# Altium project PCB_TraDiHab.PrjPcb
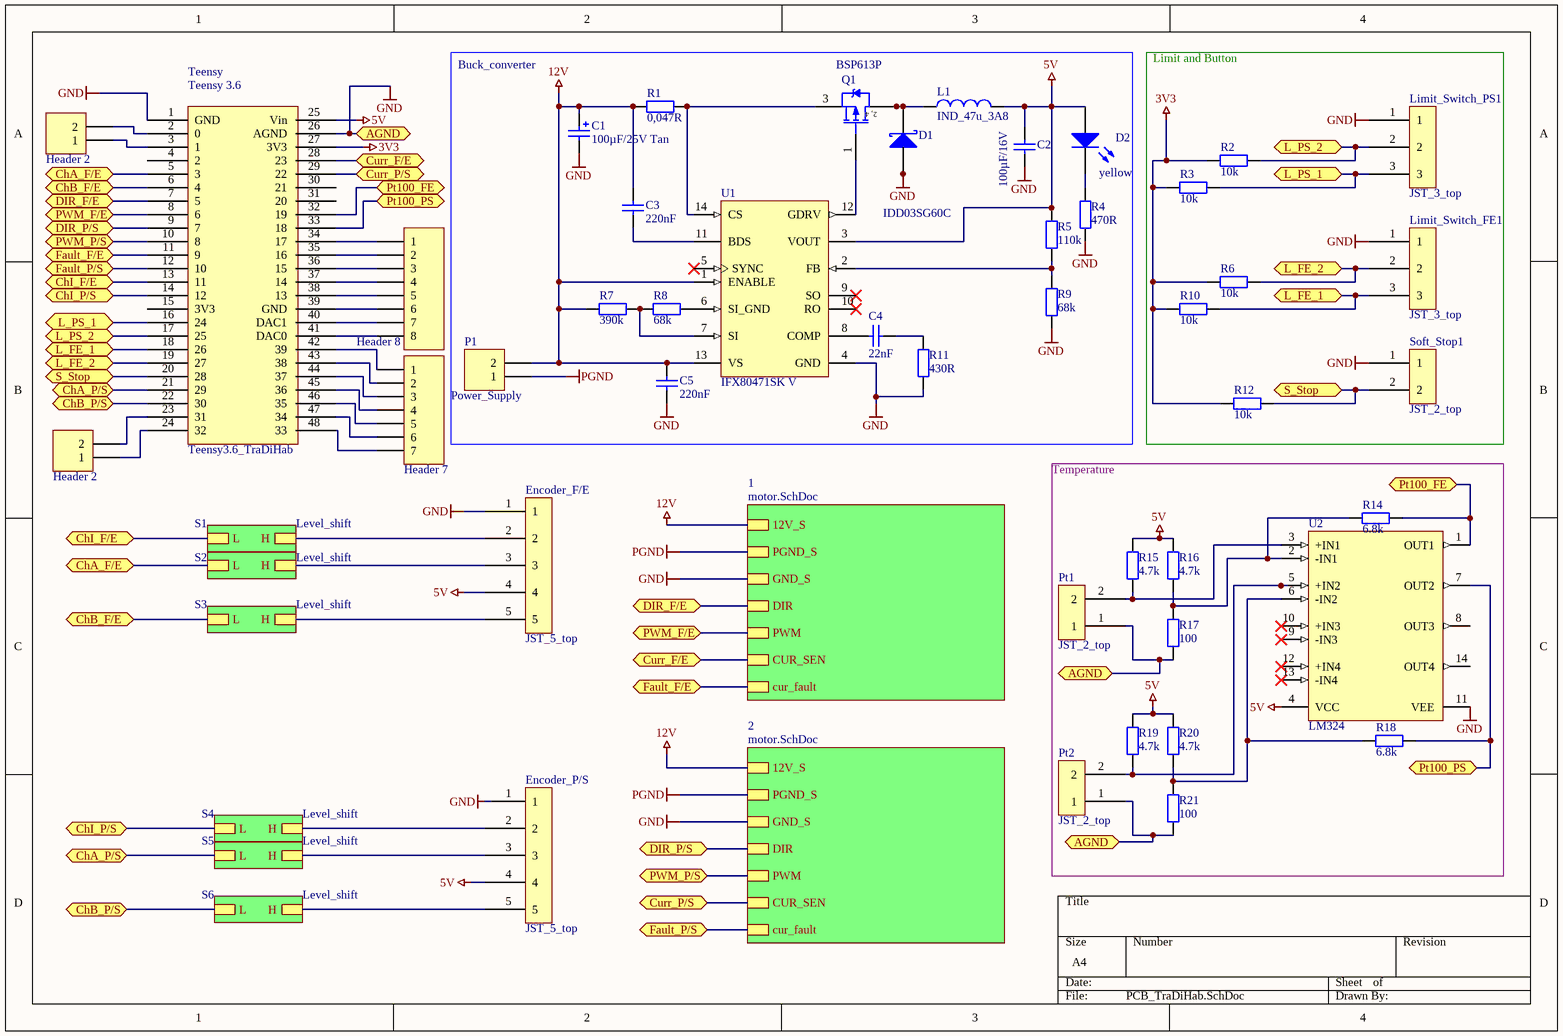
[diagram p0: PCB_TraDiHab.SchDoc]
3 sheets, 122 parts. Net scope: hierarchical (ports join the sheet entries above them; power ports are global).
Board file: 6C-2L-1550um.PcbDoc
Sheets:
  PCB_TraDiHab.SchDoc
    1 = motor.SchDoc
    2 = motor.SchDoc
    S1 = Level_shift.SchDoc
    S2 = Level_shift.SchDoc
    S3 = Level_shift.SchDoc
    S5 = Level_shift.SchDoc
    S6 = Level_shift.SchDoc
    S4 = Level_shift.SchDoc

## Sheet PCB_TraDiHab.SchDoc
size A4

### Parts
C1  100µF/25V Tan  [C]
C2  100µF/16V  [_1210]
C3  220nF  [_0805]
C4  22nF  [_0805]
C5  220nF  [_0805]
D1  IDD03SG60C  [TO_252]
D2  yellow  [LED_SMD]
Encoder_F/E  JST_5_top  [JST_5_top]
Encoder_P/S  JST_5_top  [JST_5_top]
L1  IND_47u_3A8  [WE_PD_XXL]
Limit_Switch_FE1  JST_3_top  [JST_3_top]
Limit_Switch_PS1  JST_3_top  [JST_3_top]
P1  Power_Supply  [WRTBL_2P_508]
P3  Header 8  [HDR1X8]
P4  Header 7  [HDR1X7]
P5  Header 2  [HDR1X2]
P6  Header 2  [HDR1X2]
Pt1  JST_2_top  [JST_2_top]
Pt2  JST_2_top  [JST_2_top]
Q1  BSP613P  [INF-PG-SOT223_SC-73_N]
R1  0,047R  [_1206]
R2  10k  [_0805]
R3  10k  [_0805]
R4  470R  [_0805]
R5  110k  [_0805]
R6  10k  [_0805]
R7  390k  [_0805]
R8  68k  [_0805]
R9  68k  [_0805]
R10  10k  [_0805]
R11  430R  [_0805]
R12  10k  [_0805]
R14  6.8k  [_0805]
R15  4.7k  [_0805]
R16  4.7k  [_0805]
R17  100  [_0805]
R18  6.8k  [_0805]
R19  4.7k  [_0805]
R20  4.7k  [_0805]
R21  100  [_0805]
Soft_Stop1  JST_2_top  [JST_2_top]
Teensy  Teensy3.6_TraDiHab  [teensy3_6footprint]
U1  IFX80471SK V  [INF-PG-DSO-14-1_N]
U2  LM324  [SO_14]

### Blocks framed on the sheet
Buck_converter: C1-C5 D1 D2 L1 P1 Q1 R1 R4 R5 R7-R9 R11 U1
Limit and Button: Limit_Switch_FE1 Limit_Switch_PS1 R2 R3 R6 R10 R12 Soft_Stop1
Temperature: Pt1 Pt2 R14-R21 U2

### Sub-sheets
1 = motor.SchDoc: PGND_S, GND_S, PWM, CUR_SEN, DIR, 12V_S, cur_fault
2 = motor.SchDoc: PGND_S, GND_S, PWM, CUR_SEN, DIR, 12V_S, cur_fault
S1 = Level_shift: L, H
S2 = Level_shift: L, H
S3 = Level_shift: L, H
S4 = Level_shift: L, H
S5 = Level_shift: L, H
S6 = Level_shift: L, H

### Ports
AGND, ChA_F/E, ChA_P/S, ChB_F/E, ChB_P/S, ChI_F/E, ChI_P/S, Curr_F/E, Curr_P/S, DIR_F/E, DIR_P/S, Fault_F/E, Fault_P/S, L_FE_1, L_FE_2, L_PS_1, L_PS_2, Pt100_FE, Pt100_PS, PWM_F/E, PWM_P/S, S_Stop

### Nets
3V3: R2.1 R3.1 R6.1 R10.1 R12.1 Teensy.27(3V3)
5V: C2.2 D2.1 Encoder_F/E.4 Encoder_P/S.4 L1.2 R5.2 R15.2 R16.2 R19.2 R20.2 Teensy.25(Vin) U1.3(VOUT) U2.4(VCC)
12V: C1.1 C3.2 C5.2 P1.2 R1.1 R7.1 U1.1(ENABLE) U1.13(VS) ; sheet 1/12V_S, sheet 2/12V_S  [project net V+]
GND: C1.2 C2.1 C5.1 D1.1 D1.2 Encoder_F/E.1 Encoder_P/S.1 Limit_Switch_FE1.1 Limit_Switch_PS1.1 Pt1.1 Pt2.1 R4.1 R9.1 R11.2 R17.1 R21.1 Soft_Stop1.1 Teensy.1(GND) Teensy.26(AGND) U1.4(GND) U2.11(VEE) ; port AGND, sheet 1/GND_S, sheet 2/GND_S
PGND: P1.1 ; sheet 1/PGND_S, sheet 2/PGND_S
NetC3_1: C3.1 U1.11(BDS)
NetC4_1: C4.1 U1.8(COMP)
NetC4_2: C4.2 R11.1
NetD1_3: D1.3 L1.1 Q1.2(DRAIN) Q1.4(DRAIN)
NetD2_2: D2.2 R4.2
NetEncoder_F/E_2: Encoder_F/E.2 ; sheet S1/H
NetEncoder_F/E_3: Encoder_F/E.3 ; sheet S2/H
NetEncoder_F/E_5: Encoder_F/E.5 ; sheet S3/H
NetEncoder_P/S_2: Encoder_P/S.2 ; sheet S4/H
NetEncoder_P/S_3: Encoder_P/S.3 ; sheet S5/H
NetEncoder_P/S_5: Encoder_P/S.5 ; sheet S6/H
NetIC1_1_6: Teensy.11(9) ; port Fault_F/E, sheet 1/cur_fault
NetIC1_1_7: Teensy.28(23) ; port Curr_F/E, sheet 1/CUR_SEN
NetIC1_2_6: Teensy.12(10) ; port Fault_P/S, sheet 2/cur_fault
NetIC1_2_7: Teensy.29(22) ; port Curr_P/S, sheet 2/CUR_SEN
NetIC2_1_19: Teensy.7(5) ; port DIR_F/E, sheet 1/DIR
NetIC2_1_23: Teensy.8(6) ; port PWM_F/E, sheet 1/PWM
NetIC2_2_19: Teensy.9(7) ; port DIR_P/S, sheet 2/DIR
NetIC2_2_23: Teensy.10(8) ; port PWM_P/S, sheet 2/PWM
NetLimit_Switch_FE1_2: Limit_Switch_FE1.2 R6.2 Teensy.19(27) ; port L_FE_2
NetLimit_Switch_FE1_3: Limit_Switch_FE1.3 R10.2 Teensy.18(26) ; port L_FE_1
NetLimit_Switch_PS1_2: Limit_Switch_PS1.2 R2.2 Teensy.17(25) ; port L_PS_2
NetLimit_Switch_PS1_3: Limit_Switch_PS1.3 R3.2 Teensy.16(24) ; port L_PS_1
NetP3_1: P3.1 Teensy.34(17)
NetP3_2: P3.2 Teensy.35(16)
NetP3_3: P3.3 Teensy.36(15)
NetP3_4: P3.4 Teensy.37(14)
NetP3_5: P3.5 Teensy.38(13)
NetP3_6: P3.6 Teensy.39(GND)
NetP3_7: P3.7 Teensy.40(DAC1)
NetP3_8: P3.8 Teensy.41(DAC0)
NetP4_1: P4.1 Teensy.42(39)
NetP4_2: P4.2 Teensy.43(38)
NetP4_3: P4.3 Teensy.44(37)
NetP4_4: P4.4 Teensy.45(36)
NetP4_5: P4.5 Teensy.46(35)
NetP4_6: P4.6 Teensy.47(34)
NetP4_7: P4.7 Teensy.48(33)
NetP5_1: P5.1 Teensy.3(1)
NetP5_2: P5.2 Teensy.2(0)
NetP6_1: P6.1 Teensy.24(32)
NetP6_2: P6.2 Teensy.23(31)
NetPt1_2: Pt1.2 R15.1 U2.3(+IN1)
NetPt2_2: Pt2.2 R19.1 U2.5(+IN2)
NetQ1_1: Q1.1(GATE) U1.12(GDRV)
NetQ1_3: Q1.3(SOURCE) R1.2 U1.14(CS)
NetQ6_S1_2: Teensy.13(11) ; port ChI_F/E, sheet S1/L
NetQ6_S2_2: Teensy.5(3) ; port ChA_F/E, sheet S2/L
NetQ6_S3_2: Teensy.6(4) ; port ChB_F/E, sheet S3/L
NetQ6_S4_2: Teensy.14(12) ; port ChI_P/S, sheet S4/L
NetQ6_S5_2: Teensy.21(29) ; port ChA_P/S, sheet S5/L
NetQ6_S6_2: Teensy.22(30) ; port ChB_P/S, sheet S6/L
NetR5_1: R5.1 R9.2 U1.2(FB)
NetR7_2: R7.2 R8.1 U1.7(SI)
NetR8_2: R8.2 U1.6(SI_GND)
NetR12_2: R12.2 Soft_Stop1.2 Teensy.20(28) ; port S_Stop
NetR14_1: R14.1 R16.1 R17.2 U2.2(-IN1)
NetR14_2: R14.2 Teensy.32(19) U2.1(OUT1) ; port Pt100_FE
NetR18_1: R18.1 R20.1 R21.2 U2.6(-IN2)
NetR18_2: R18.2 Teensy.33(18) U2.7(OUT2) ; port Pt100_PS

Not connected (* = marked no-connect by the designer): Teensy 4(2) 15(3V3) 30(21) 31(20); U1 5(SYNC)* 9(SO)* 10(RO)*; U2 8(OUT3) 9(-IN3)* 10(+IN3)* 12(+IN4)* 13(-IN4)* 14(OUT4)

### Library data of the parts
C1 = Cap_56: Name: Cap_tan_47u_25V; RS_number: 684-5284P; QR: 1; Capacity: 47u; Voltage: 25v
C2 = Cap_65: Name: Cap_1210; Capacity: ?F; Voltage: ?V
C3 C5 = Cap_63: Name: Cap_0805; Capacity: ?F; Voltage: ?V
C4 = Cap_129: Name: Cap_0603; QR: 0
D1 = DIODE_12: Type: Schottky; Current / Power: 3.5 A; RS_number: 300-357P; QR: 0
D2 = DIODE_60: Name: LED_0603_blau; Colour: blau; RS_number: 697-3610P; QR: 0
L1 = Ind_8: Inductor; Wuerth_number: 744 7709 470; QR: 0; Inductivity: 47 uH; Current: 3.8 A
P1 = Con_7: RS_number: 193-0586; QR: 0
P3 = Con_38: QR: 0
P4 = Con_37: QR: 0
P5 P6 = Con_32: QR: 0
Q1 = Tran_33: P-Channel SIPMOS Small-Signal-Transistor, -60 V VDS, -2.9 A ID, -55 to 150 degC, PG-SOT223 (SC-73), Reel, Green; Manufacturer: Infineon; Green: TRUE; ID (max): -2.9 A; IDpuls (max): -11.6 A; Mode: Enhancement; Polarity: P; Pto t (max): 1.8 W; QG: -22 nC; RDS (on) (max): 130 mOhm; Rth: 100 K/W; VDS (max): -60 V; VGS(th) (max): -4 V; VGS(th) (min): -2.1 V
R1 = Res_7: Name: Res_1206
R2 R3 R6 R10 R12 R14-R21 = Res_6: Name: Res_0805
R4 R5 R7-R9 R11 = Res_5: Name: Res_0603
U1 = IFX80471SK V: Step-Down DC/DC Controller, 2,300 mA Iq, -40 to 125 degC, PG-DSO-14-1, Reel, Green; Manufacturer: Infineon; Green: TRUE; Iq (typ): 130 uA; Max Number Reflow: 3; Max Peak Reflow Temp: 260 degC; Output: Buck Converter; Tolerance: 3(5)%; VQ (max): adjustable
U2 = IC_46: RS_number: 536-0925; IC_description: OPV_4; QR: 0

## Sheet motor.SchDoc
size A4
Used 2 times, as channels 1, 2. Parts and nets are listed once, with the designators drawn on the sheet.
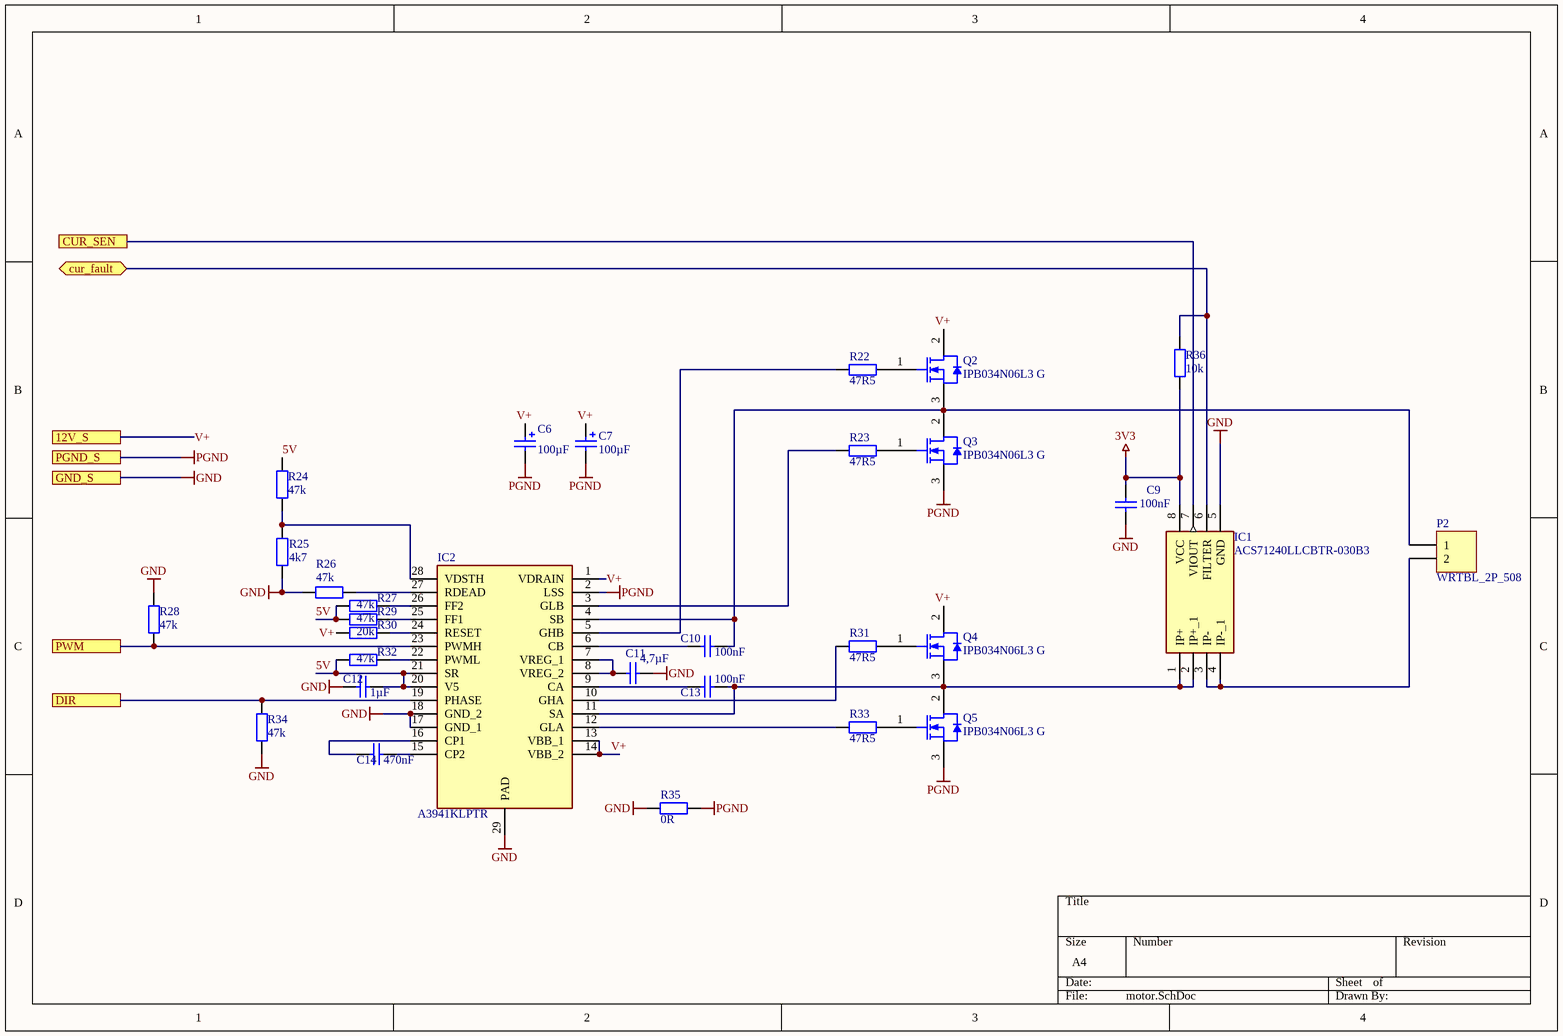
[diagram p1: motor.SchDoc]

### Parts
C6  100µF  [Cap_THT_Elko_rad_D8mm]
C7  100µF  [Cap_THT_Elko_rad_D8mm]
C9  100nF  [_0805]
C10  100nF  [_0805]
C11  4,7µF  [_0805]
C12  1µF  [_0805]
C13  100nF  [_0805]
C14  470nF  [_0805]
IC1  ACS71240LLCBTR-030B3  [SOIC127P600X175-8N]
IC2  A3941KLPTR  [SOP65P640X120-29N]
P2  WRTBL_2P_508  [WRTBL_2P_508]
Q2  IPB034N06L3 G  [INF-PG-TO-263-3-2_A_N]
Q3  IPB034N06L3 G  [INF-PG-TO-263-3-2_A_N]
Q4  IPB034N06L3 G  [INF-PG-TO-263-3-2_A_N]
Q5  IPB034N06L3 G  [INF-PG-TO-263-3-2_A_N]
R22  47R5  [_0805]
R23  47R5  [_0805]
R24  47k  [_0805]
R25  4k7  [_0805]
R26  47k  [_0805]
R27  47k  [_0805]
R28  47k  [_0805]
R29  47k  [_0805]
R30  20k  [_0805]
R31  47R5  [_0805]
R32  47k  [_0805]
R33  47R5  [_0805]
R34  47k  [_0805]
R35  0R  [_0805]
R36  10k  [_0805]

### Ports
12V_S, cur_fault, CUR_SEN, DIR, GND_S, PGND_S, PWM

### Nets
3V3: C9.2 IC1.8(VCC) R36.1
GND: C9.1 C11.2 C12.1 IC1.5(GND) IC2.17(GND_1) IC2.18(GND_2) IC2.29(PAD) R25.2 R26.2 R28.1 R34.2 R35.2 ; port GND_S
PGND: C6.2 C7.2 IC2.2(LSS) Q3.3(SOURCE) Q5.3(SOURCE) R35.1 ; port PGND_S
5V: C12.2 IC2.20(V5) IC2.21(SR) R24.1 R27.2 R29.2 R32.2
cur_fault: IC1.6(FILTER) R36.2 ; port cur_fault
CUR_SEN: IC1.7(VIOUT) ; port CUR_SEN
DIR: IC2.19(PHASE) R34.1 ; port DIR
PWM: IC2.23(PWMH) R28.2 ; port PWM
V+: C6.1 C7.1 IC2.1(VDRAIN) IC2.13(VBB_1) IC2.14(VBB_2) Q2.2(DRAIN) Q4.2(DRAIN) R30.2 ; port 12V_S
NetC10_1: C10.1 IC2.6(CB)
NetC10_2: C10.2 IC2.4(SB) P2.1 Q2.3(SOURCE) Q3.2(DRAIN)
NetC11_1: C11.1 IC2.7(VREG_1) IC2.8(VREG_2)
NetC13_1: C13.1 IC2.9(CA)
NetC13_2: C13.2 IC1.1(IP+) IC1.2(IP+_1) IC2.11(SA) Q4.3(SOURCE) Q5.2(DRAIN)
NetC14_1: C14.1 IC2.16(CP1)
NetC14_2: C14.2 IC2.15(CP2)
NetIC1_3: IC1.3(IP-) IC1.4(IP-_1) P2.2
NetIC2_3: IC2.3(GLB) R23.2
NetIC2_5: IC2.5(GHB) R22.2
NetIC2_10: IC2.10(GHA) R31.2
NetIC2_12: IC2.12(GLA) R33.2
NetIC2_22: IC2.22(PWML) R32.1
NetIC2_24: IC2.24(RESET) R30.1
NetIC2_25: IC2.25(FF1) R29.1
NetIC2_26: IC2.26(FF2) R27.1
NetIC2_27: IC2.27(RDEAD) R26.1
NetIC2_28: IC2.28(VDSTH) R24.2 R25.1
NetQ2_1: Q2.1(GATE) R22.1
NetQ3_1: Q3.1(GATE) R23.1
NetQ4_1: Q4.1(GATE) R31.1
NetQ5_1: Q5.1(GATE) R33.1

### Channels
1: designators end in _1; ports 12V_S=V+ cur_fault=NetIC1_1_6 CUR_SEN=NetIC1_1_7 DIR=NetIC2_1_19 GND_S=GND PGND_S=PGND PWM=NetIC2_1_23
2: designators end in _2; ports 12V_S=V+ cur_fault=NetIC1_2_6 CUR_SEN=NetIC1_2_7 DIR=NetIC2_2_19 GND_S=GND PGND_S=PGND PWM=NetIC2_2_23

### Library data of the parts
C6 C7 = Cap_15: Name: Cap_Elko_rad_100u_35V; RS_number: 228-6767; QR: 1; ax_rad: rad; Capacity: 100u; Voltage: 35V
C9-C11 C13 C14 = Cap_129: Name: Cap_0603; QR: 0
C12 = Cap_128: Name: Cap_0805; QR: 0
IC1 = ACS712ELCTR-20A-T: Integrated Circuit; Manufacturer_Name: Allegro Microsystems; Allied_Number: R1076682
IC2 = A3941KLPTR: Integrated Circuit; Manufacturer_Name: Allegro Microsystems
P2 = Con_7: RS_number: 193-0586; QR: 0
Q2-Q5 = IPB034N06L3 G: N-Channel OptiMOS 3 Power-Transistor, 60 V VDS, 90 A ID, -55 to 175 degC, PG-TO-263-3-2, Reel, Green; Manufacturer: Infineon; Green: TRUE; ID (max): 90 A; IDpuls (max): 360 A; Polarity: N; Ptot (max): 167 W; QG: 59 nC; RDS (on) (max): 3.7 mOhm; RDS (on) (max) (@4.5V): 5.7 mOhm; Rth: 0.9 K/W; RthJA (max): 62 K/W; VDS (max): 60 V; VGS(th) (max): 2.2 V; VGS(th) (min): 1.2 V
R22-R35 = Res_5: Name: Res_0603
R36 = Res_6: Name: Res_0805

## Sheet Level_shift.SchDoc
size A4
Used 6 times, as channels S1, S2, S3, S5, S6, S4. Parts and nets are listed once, with the designators drawn on the sheet.
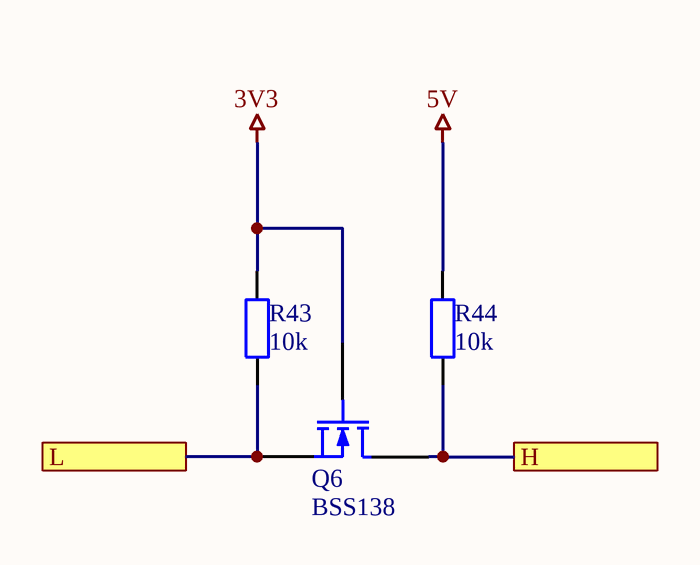
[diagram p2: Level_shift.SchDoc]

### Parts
Q6  BSS138  [SOT_23]
R43  10k  [_0805]
R44  10k  [_0805]

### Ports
H, L

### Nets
3V3: Q6.1(G) R43.2
5V: R44.2
H: Q6.3(D) R44.1 ; port H
L: Q6.2(S) R43.1 ; port L

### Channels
S1: designators end in _S1; ports H=NetEncoder_F/E_2 L=NetQ6_S1_2
S2: designators end in _S2; ports H=NetEncoder_F/E_3 L=NetQ6_S2_2
S3: designators end in _S3; ports H=NetEncoder_F/E_5 L=NetQ6_S3_2
S5: designators end in _S5; ports H=NetEncoder_P/S_3 L=NetQ6_S5_2
S6: designators end in _S6; ports H=NetEncoder_P/S_5 L=NetQ6_S6_2
S4: designators end in _S4; ports H=NetEncoder_P/S_2 L=NetQ6_S4_2

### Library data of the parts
Q6 = Tran_11: Name: ZXMN2A; RS_number: 669-7685P; QR: 0; Type: N; Current: 2.2 A
R43 R44 = Res_6: Name: Res_0805

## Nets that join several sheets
3V3: PCB_TraDiHab (6 pins), 1 (C9_1.2 IC1_1.8 R36_1.1), 2 (C9_2.2 IC1_2.8 R36_2.1), S1 (Q6_S1.1 R43_S1.2), S2 (Q6_S2.1 R43_S2.2), S3 (Q6_S3.1 R43_S3.2), S5 (Q6_S5.1 R43_S5.2), S6 (Q6_S6.1 R43_S6.2), S4 (Q6_S4.1 R43_S4.2)
5V: PCB_TraDiHab (13 pins), S1 (R44_S1.2), S2 (R44_S2.2), S3 (R44_S3.2), S5 (R44_S5.2), S6 (R44_S6.2), S4 (R44_S4.2)
GND: PCB_TraDiHab (21 pins), 1 (12 pins), 2 (12 pins)
PGND: PCB_TraDiHab (P1.1), 1 (6 pins), 2 (6 pins)
V+: PCB_TraDiHab (8 pins), 1 (8 pins), 2 (8 pins)
NetEncoder_F/E_2: PCB_TraDiHab (Encoder_F/E.2), S1 (Q6_S1.3 R44_S1.1)
NetEncoder_F/E_3: PCB_TraDiHab (Encoder_F/E.3), S2 (Q6_S2.3 R44_S2.1)
NetEncoder_F/E_5: PCB_TraDiHab (Encoder_F/E.5), S3 (Q6_S3.3 R44_S3.1)
NetEncoder_P/S_2: PCB_TraDiHab (Encoder_P/S.2), S4 (Q6_S4.3 R44_S4.1)
NetEncoder_P/S_3: PCB_TraDiHab (Encoder_P/S.3), S5 (Q6_S5.3 R44_S5.1)
NetEncoder_P/S_5: PCB_TraDiHab (Encoder_P/S.5), S6 (Q6_S6.3 R44_S6.1)
NetIC1_1_6: PCB_TraDiHab (Teensy.11), 1 (IC1_1.6 R36_1.2)
NetIC1_1_7: PCB_TraDiHab (Teensy.28), 1 (IC1_1.7)
NetIC1_2_6: PCB_TraDiHab (Teensy.12), 2 (IC1_2.6 R36_2.2)
NetIC1_2_7: PCB_TraDiHab (Teensy.29), 2 (IC1_2.7)
NetIC2_1_19: PCB_TraDiHab (Teensy.7), 1 (IC2_1.19 R34_1.1)
NetIC2_1_23: PCB_TraDiHab (Teensy.8), 1 (IC2_1.23 R28_1.2)
NetIC2_2_19: PCB_TraDiHab (Teensy.9), 2 (IC2_2.19 R34_2.1)
NetIC2_2_23: PCB_TraDiHab (Teensy.10), 2 (IC2_2.23 R28_2.2)
NetQ6_S1_2: PCB_TraDiHab (Teensy.13), S1 (Q6_S1.2 R43_S1.1)
NetQ6_S2_2: PCB_TraDiHab (Teensy.5), S2 (Q6_S2.2 R43_S2.1)
NetQ6_S3_2: PCB_TraDiHab (Teensy.6), S3 (Q6_S3.2 R43_S3.1)
NetQ6_S4_2: PCB_TraDiHab (Teensy.14), S4 (Q6_S4.2 R43_S4.1)
NetQ6_S5_2: PCB_TraDiHab (Teensy.21), S5 (Q6_S5.2 R43_S5.1)
NetQ6_S6_2: PCB_TraDiHab (Teensy.22), S6 (Q6_S6.2 R43_S6.1)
